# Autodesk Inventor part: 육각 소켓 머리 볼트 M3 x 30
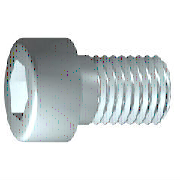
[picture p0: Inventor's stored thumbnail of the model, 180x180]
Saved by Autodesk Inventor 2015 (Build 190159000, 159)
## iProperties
IsCustomPart: 1
Created: 2012-02
Part Number: 육각 소켓 머리 볼트 M3 x 30
Material: 강철, 연강
Description: 6각 소켓 머리 캡 나사
Document SubType Name: Modeling
Standard: ISO 4762
Designer: mdu-01
Standard Revision: Fourth edition 2004-03-01
Standards Organization: ISO
Language: ko-KR
Size Designation: M3 x 30
Categories: <MemberInstance><Categories><Category DisplayName="조임쇠" InternalName="e4da775c-781d-43d5-af7c-5136215cf5a6" Mnemonic="FSTN"><Category DisplayName="볼트" InternalN
Density: 7.75 g/cm^3
Appearance: 강철
Author: mdu-01
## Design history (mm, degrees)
sketch "스케치1"
  geometry: L1 (-0.867, 0)-(30, 0); L2 (30, 0)-(30, 1.5); L3 (30, 1.5)-(12, 1.5); L4 (12, 1.5)-(11.693, 1.5); L5 (11.693, 1.5)-(0, 1.5); L6 (0, 1.5)-(0, 2.75); L7 (0, 2.75)-(-3, 2.75); L8 (-3, 2.75)-(-3, 1.443); L9 (-3, 1.443)-(-1.7, 1.443); L10 (-1.7, 1.443)-(-0.867, 0); L11 (-9.6, 0)-(36.6, 0) reference; L12 (0, -0.55)-(0, 3.3) reference; L13 (12, 1.5)-(0, 1.5)
  constraints: 22 end point, 6 parallel, 2 collinear, 2 perpendicular, 1 horizontal, 1 point on line
  dimensions: "d1" = 18 distance from line of L3.end L2 (= GEL); "d2" = 0.30683 distance of L4.end L3.end (computed from GAL); "d3" = 3 distance between parallel lines of L8 L6 (= KOH); "d4" = 1.3 distance of L8.end L9.end (= INTI); "d5" = 60 deg angle of L10 L1; "d6" = 3 diameter of L3 L1 (= GD); "d7" = 3 diameter of L5 L1 (= BDM); "d8" = 2.88675 diameter of L9 L1 (= 1.1547 x SW); "d9" = 5.5 diameter of L7 L1 (= KOD); "d26" = 30 distance between parallel lines of L12 L2 (= NLG)
revolve "본체" sketch "스케치1" stored, may be unused: angle "d10" = 90 deg
sketch "스케치2"
  geometry: L1 (0, -3.85)-(0, 3.85) reference; L2 (-3.85, 0)-(3.85, 0) reference; L3 (1.443, 0)-(0.722, -1.25); L4 (0.722, -1.25)-(-0.722, -1.25); L5 (-0.722, -1.25)-(-1.443, 0); L6 (-1.443, 0)-(-0.722, 1.25); L7 (-0.722, 1.25)-(0.722, 1.25); L8 (0.722, 1.25)-(1.443, 0); 2 further points
  constraints: 12 end point, 1 coincident, 1 horizontal alignment, 1 point on line, 12 other
extrude "슬롯" join sketch "스케치2" stored distance "d11" = 10; taper "d12" = 0 deg
workplane "Work Plane1"
fillet "Fillet2" dims "d30" = 0.1 (= R)
body "Solid1"
fillet "모깎기1" dims "d17" = 0.3 (= RR)
feature "스레드" dims "d13" = 18 (= GEL), "d14" = 0
chamfer "모따기1" distance "d15" = 0.30673 (= -0.5 x SPD + 0.5 x GD); stored, may be unused: second distance "d16" = 0.30673 (= GUL), angle "d27" = 45 deg
other parameters: "GD" = 3 [user parameter; used in 2 equation terms], "NLG" = 30 [user parameter; used in 1 equation term], "GEL" = 18 [user parameter; used in 2 equation terms], "KOD" = 5.5 [user parameter; used in 1 equation term], "KOH" = 3 [user parameter; used in 1 equation term], "INTI" = 1.3 [user parameter; used in 1 equation term], "GAL" = 0.30673 (= 0.61345 x PTC) [user parameter; used in 1 equation term], "GUL" = 0.30673 (= 0.61345 x PTC) [user parameter; used in 1 equation term], "BDM" = 3 (= NND) [user parameter; used in 1 equation term], "SW" = 2.5 [user parameter; used in 2 equation terms], "RR" = 0.3 [user parameter; used in 1 equation term], "SPD" = 2.38655 (= NND - 1.2269 x PTC) [user parameter; used in 1 equation term], "d19" = 0, "d28" = 0, "d29" = 0, "R" = 0.1 [user parameter; used in 1 equation term], "TOA" = 30 deg [user parameter], "GD1" = 2.38655 (= THREADDIA - 1.2269 x PTC) [user parameter], "THREADDIA" = 3 [user parameter; used in 1 equation term], "FAWI" = 45 deg [user parameter], "PTC" = 0.5 [user parameter; used in 5 equation terms], "NND" = 3 [user parameter; used in 2 equation terms], "E0" = 2.8875 (= 1.155 x SW) [user parameter]
